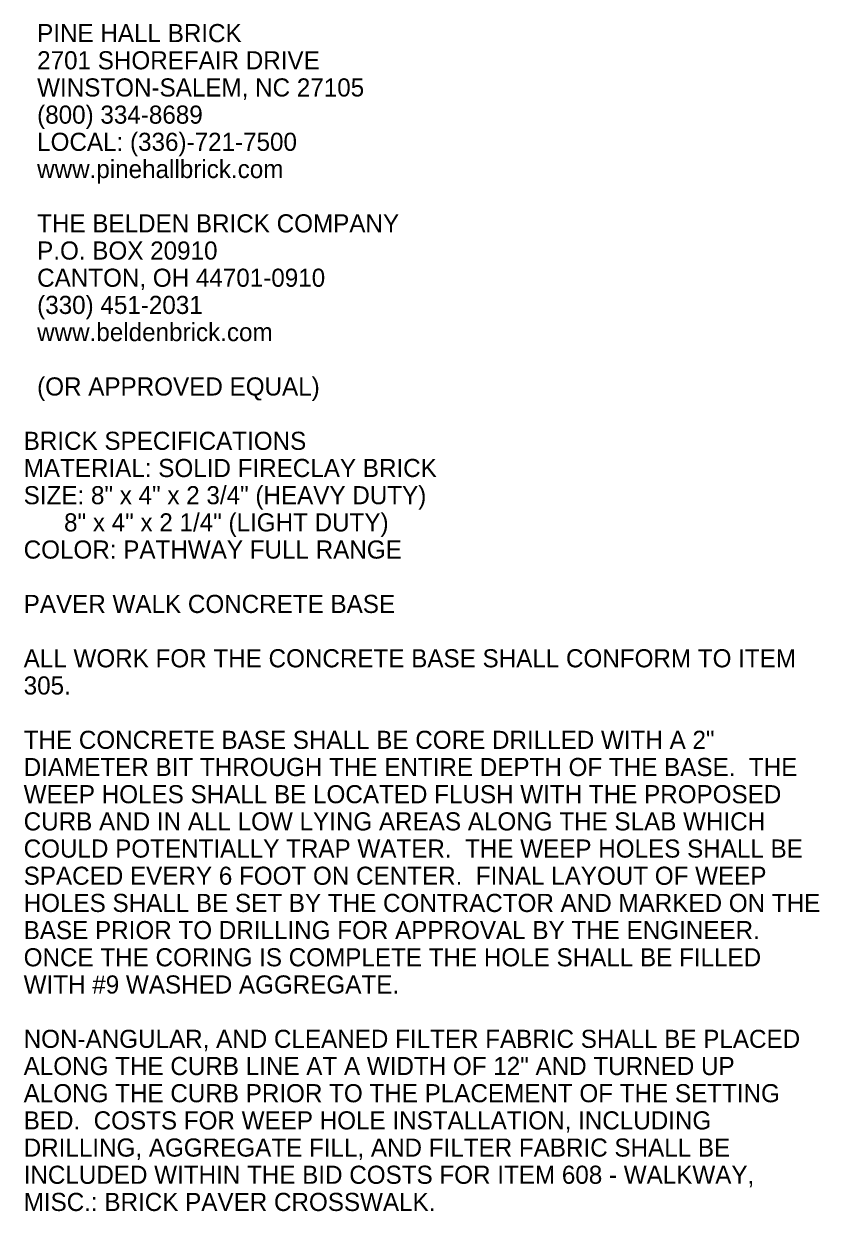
# Model space of a CAD drawing. Extents: x -848 to 1, y -1131 to -115.
# Drawn here: x -281.1 to -219.6, y -718.1 to -626.3 of the extents above; entities that cross this region are included whole.
import ezdxf

# ---------------------------------------------------------------- set-up
doc = ezdxf.new("R2010")
doc.units = 0
doc.layers.add('SH_Text', color=7, linetype='Continuous')

msp = doc.modelspace()

# ---------------------------------------------------------------- texts
at = {"layer": 'SH_Text'}
for s, p in [('  PINE HALL BRICK', (-281.085, -627.756)), ('  2701 SHOREFAIR DRIVE', (-281.085, -629.856)), ('  WINSTON-SALEM, NC 27105', (-281.085, -631.956)), ('  (800) 334-8689', (-281.085, -634.056)), ('  LOCAL: (336)-721-7500', (-281.085, -636.156)), ('  www.pinehallbrick.com', (-281.085, -638.256)), ('  THE BELDEN BRICK COMPANY', (-281.085, -642.456)), ('  P.O. BOX 20910', (-281.085, -644.556)), ('  CANTON, OH 44701-0910', (-281.085, -646.656)), ('  (330) 451-2031', (-281.085, -648.756)), ('  www.beldenbrick.com', (-281.085, -650.856)), ('  (OR APPROVED EQUAL)', (-281.085, -655.056)), ('BRICK SPECIFICATIONS', (-281.085, -659.256)), ('MATERIAL: SOLID FIRECLAY BRICK', (-281.085, -661.356)), ('SIZE: 8" x 4" x 2 3/4" (HEAVY DUTY)', (-281.085, -663.456)), ('      8" x 4" x 2 1/4" (LIGHT DUTY)', (-281.085, -665.556)), ('COLOR: PATHWAY FULL RANGE', (-281.085, -667.656)), ('PAVER WALK CONCRETE BASE', (-281.085, -671.856)), ('ALL WORK FOR THE CONCRETE BASE SHALL CONFORM TO ITEM ', (-281.085, -676.056)), ('305.', (-281.085, -678.156)), ('THE CONCRETE BASE SHALL BE CORE DRILLED WITH A 2" ', (-281.085, -682.356)), ('DIAMETER BIT THROUGH THE ENTIRE DEPTH OF THE BASE.  THE ', (-281.085, -684.456)), ('WEEP HOLES SHALL BE LOCATED FLUSH WITH THE PROPOSED ', (-281.085, -686.556)), ('CURB AND IN ALL LOW LYING AREAS ALONG THE SLAB WHICH ', (-281.085, -688.656)), ('COULD POTENTIALLY TRAP WATER.  THE WEEP HOLES SHALL BE ', (-281.085, -690.756)), ('SPACED EVERY 6 FOOT ON CENTER.  FINAL LAYOUT OF WEEP ', (-281.085, -692.856)), ('HOLES SHALL BE SET BY THE CONTRACTOR AND MARKED ON THE ', (-281.085, -694.956)), ('BASE PRIOR TO DRILLING FOR APPROVAL BY THE ENGINEER.  ', (-281.085, -697.056)), ('ONCE THE CORING IS COMPLETE THE HOLE SHALL BE FILLED ', (-281.085, -699.156)), ('WITH #9 WASHED AGGREGATE.', (-281.085, -701.256)), ('NON-ANGULAR, AND CLEANED FILTER FABRIC SHALL BE PLACED ', (-281.085, -705.456)), ('ALONG THE CURB LINE AT A WIDTH OF 12" AND TURNED UP ', (-281.085, -707.556)), ('ALONG THE CURB PRIOR TO THE PLACEMENT OF THE SETTING ', (-281.085, -709.656)), ('BED.  COSTS FOR WEEP HOLE INSTALLATION, INCLUDING ', (-281.085, -711.756)), ('DRILLING, AGGREGATE FILL, AND FILTER FABRIC SHALL BE ', (-281.085, -713.856)), ('INCLUDED WITHIN THE BID COSTS FOR ITEM 608 - WALKWAY, ', (-281.085, -715.956)), ('MISC.: BRICK PAVER CROSSWALK.', (-281.085, -718.056))]:
    msp.add_text(s, height=1.4, dxfattribs=at).set_placement(p)

doc.saveas('drawing.dxf')
